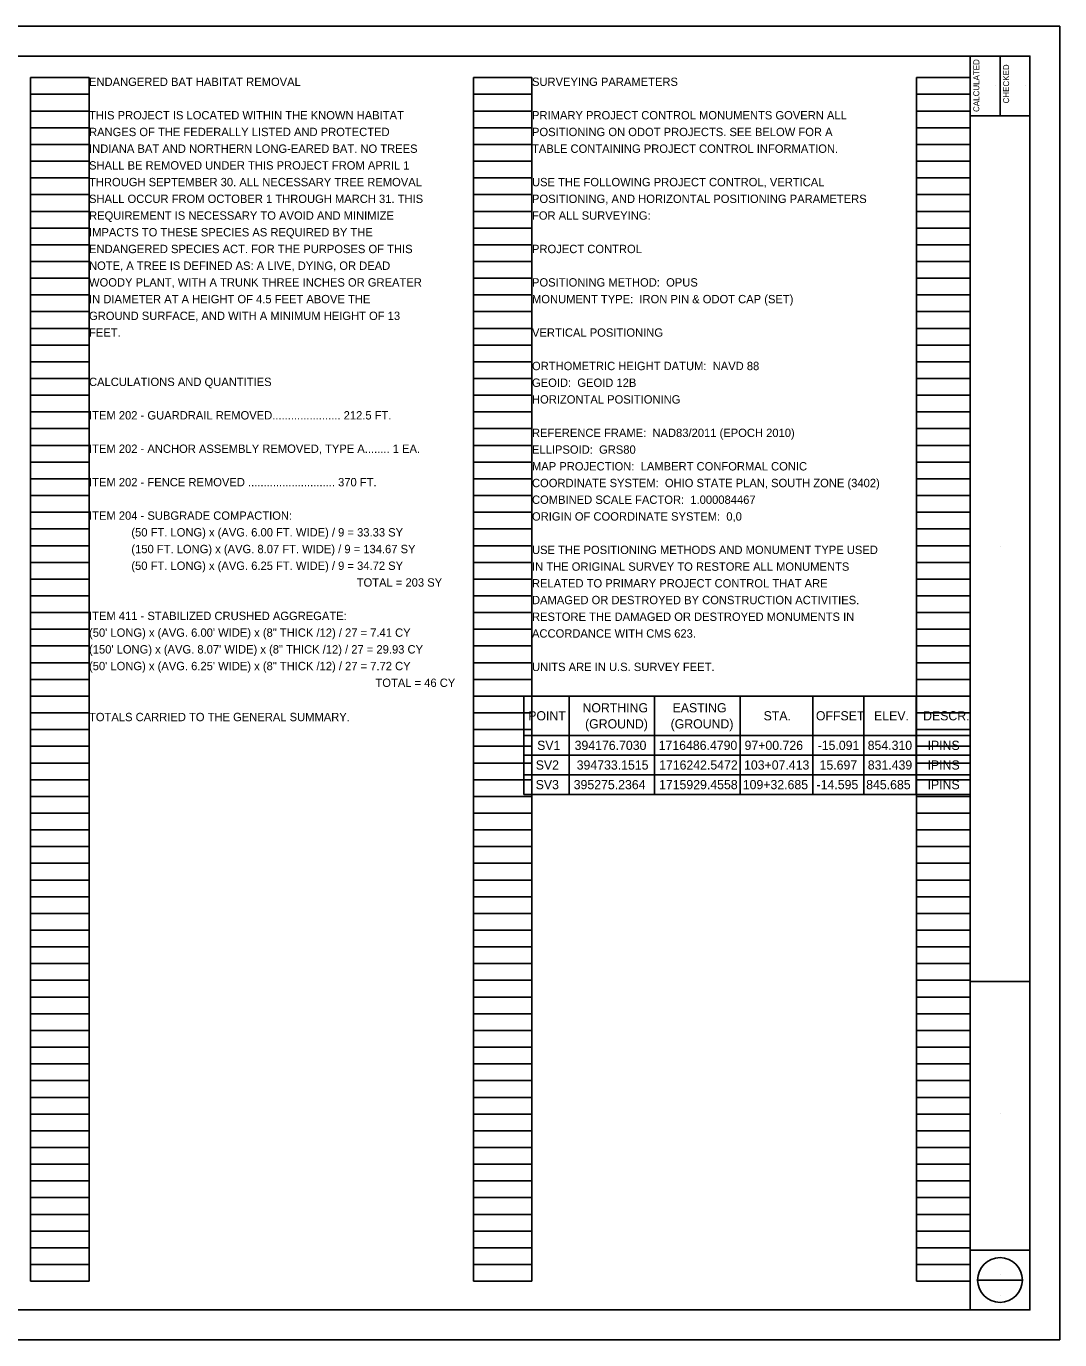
# Model space of a CAD drawing. Extents: x 0 to 34, y 0 to 22.
# Drawn here: x 16.69 to 34, y 0 to 22 of the extents above; entities that cross this region are included whole.
import ezdxf

# ---------------------------------------------------------------- set-up
doc = ezdxf.new("R2010")
doc.units = 0
for name, color, linetype in [('SH_Border', 7, 'Continuous'), ('SH_Cut_Line', 7, 'Continuous'), ('SH_Data', 7, 'Continuous'), ('SH_Text', 7, 'Continuous')]:
    doc.layers.add(name, color=color, linetype=linetype)

msp = doc.modelspace()

# ---------------------------------------------------------------- linework, layer by layer
at = {"layer": 'SH_Border'}
for p, q in [((32.5, 0.5), (32.5, 21.5)), ((33, 21.5), (33, 20.5)), ((32.5, 20.5), (33.5, 20.5)), ((32.5, 6), (33.5, 6)), ((32.5, 1.5), (33.5, 1.5))]:
    msp.add_line(p, q, dxfattribs=at)
msp.add_lwpolyline([(2, 21.5), (33.5, 21.5), (33.5, 0.5), (2, 0.5)], close=True, dxfattribs=at)
at = {"layer": 'SH_Cut_Line'}
msp.add_lwpolyline([(0, 0), (34, 0), (34, 22), (0, 22)], close=True, dxfattribs=at)
at = {"layer": 'SH_Data'}
for p, q in [((16.76, 0.98), (16.76, 21.14)), ((16.76, 21.14), (17.74, 21.14)), ((17.74, 0.98), (17.74, 21.14)), ((24.18, 0.98), (24.18, 21.14)), ((24.18, 21.14), (25.16, 21.14)), ((25.16, 0.98), (25.16, 21.14)), ((31.6, 0.98), (31.6, 21.14)), ((31.6, 21.14), (32.5, 21.14)), ((32.5, 0.98), (32.5, 21.14)), ((32.92, 21.004), (32.92, 21.004)), ((33.42, 21.004), (33.42, 21.004)), ((16.76, 20.86), (17.74, 20.86)), ((24.18, 20.86), (25.16, 20.86)), ((31.6, 20.86), (32.5, 20.86)), ((16.76, 20.58), (17.74, 20.58)), ((24.18, 20.58), (25.16, 20.58)), ((31.6, 20.58), (32.5, 20.58)), ((16.76, 20.3), (17.74, 20.3)), ((24.18, 20.3), (25.16, 20.3)), ((31.6, 20.3), (32.5, 20.3)), ((16.76, 20.02), (17.74, 20.02)), ((24.18, 20.02), (25.16, 20.02)), ((31.6, 20.02), (32.5, 20.02)), ((16.76, 19.74), (17.74, 19.74)), ((24.18, 19.74), (25.16, 19.74)), ((31.6, 19.74), (32.5, 19.74)), ((16.76, 19.46), (17.74, 19.46)), ((24.18, 19.46), (25.16, 19.46)), ((31.6, 19.46), (32.5, 19.46)), ((16.76, 19.18), (17.74, 19.18)), ((24.18, 19.18), (25.16, 19.18)), ((31.6, 19.18), (32.5, 19.18)), ((16.76, 18.9), (17.74, 18.9)), ((24.18, 18.9), (25.16, 18.9)), ((31.6, 18.9), (32.5, 18.9)), ((16.76, 18.62), (17.74, 18.62)), ((24.18, 18.62), (25.16, 18.62)), ((31.6, 18.62), (32.5, 18.62)), ((16.76, 18.34), (17.74, 18.34)), ((24.18, 18.34), (25.16, 18.34)), ((31.6, 18.34), (32.5, 18.34)), ((16.76, 18.06), (17.74, 18.06)), ((24.18, 18.06), (25.16, 18.06)), ((31.6, 18.06), (32.5, 18.06)), ((16.76, 17.78), (17.74, 17.78)), ((24.18, 17.78), (25.16, 17.78)), ((31.6, 17.78), (32.5, 17.78)), ((16.76, 17.5), (17.74, 17.5)), ((24.18, 17.5), (25.16, 17.5)), ((31.6, 17.5), (32.5, 17.5)), ((16.76, 17.22), (17.74, 17.22)), ((24.18, 17.22), (25.16, 17.22)), ((31.6, 17.22), (32.5, 17.22)), ((16.76, 16.94), (17.74, 16.94)), ((24.18, 16.94), (25.16, 16.94)), ((31.6, 16.94), (32.5, 16.94)), ((16.76, 16.66), (17.74, 16.66)), ((24.18, 16.66), (25.16, 16.66)), ((31.6, 16.66), (32.5, 16.66)), ((16.76, 16.38), (17.74, 16.38)), ((24.18, 16.38), (25.16, 16.38)), ((31.6, 16.38), (32.5, 16.38)), ((16.76, 16.1), (17.74, 16.1)), ((24.18, 16.1), (25.16, 16.1)), ((31.6, 16.1), (32.5, 16.1)), ((16.76, 15.82), (17.74, 15.82)), ((24.18, 15.82), (25.16, 15.82)), ((31.6, 15.82), (32.5, 15.82)), ((16.76, 15.54), (17.74, 15.54)), ((24.18, 15.54), (25.16, 15.54)), ((31.6, 15.54), (32.5, 15.54)), ((16.76, 15.26), (17.74, 15.26)), ((24.18, 15.26), (25.16, 15.26)), ((31.6, 15.26), (32.5, 15.26)), ((16.76, 14.98), (17.74, 14.98)), ((24.18, 14.98), (25.16, 14.98)), ((31.6, 14.98), (32.5, 14.98)), ((16.76, 14.7), (17.74, 14.7)), ((24.18, 14.7), (25.16, 14.7)), ((31.6, 14.7), (32.5, 14.7)), ((16.76, 14.42), (17.74, 14.42)), ((24.18, 14.42), (25.16, 14.42)), ((31.6, 14.42), (32.5, 14.42)), ((16.76, 14.14), (17.74, 14.14)), ((24.18, 14.14), (25.16, 14.14)), ((31.6, 14.14), (32.5, 14.14)), ((16.76, 13.86), (17.74, 13.86)), ((24.18, 13.86), (25.16, 13.86)), ((31.6, 13.86), (32.5, 13.86)), ((16.76, 13.58), (17.74, 13.58)), ((24.18, 13.58), (25.16, 13.58)), ((31.6, 13.58), (32.5, 13.58)), ((16.76, 13.3), (17.74, 13.3)), ((24.18, 13.3), (25.16, 13.3)), ((31.6, 13.3), (32.5, 13.3)), ((33, 13.292), (33, 13.292)), ((16.76, 13.02), (17.74, 13.02)), ((24.18, 13.02), (25.16, 13.02)), ((31.6, 13.02), (32.5, 13.02)), ((16.76, 12.74), (17.74, 12.74)), ((24.18, 12.74), (25.16, 12.74)), ((31.6, 12.74), (32.5, 12.74)), ((16.76, 12.46), (17.74, 12.46)), ((24.18, 12.46), (25.16, 12.46)), ((31.6, 12.46), (32.5, 12.46)), ((16.76, 12.18), (17.74, 12.18)), ((24.18, 12.18), (25.16, 12.18)), ((31.6, 12.18), (32.5, 12.18)), ((16.76, 11.9), (17.74, 11.9)), ((24.18, 11.9), (25.16, 11.9)), ((31.6, 11.9), (32.5, 11.9)), ((16.76, 11.62), (17.74, 11.62)), ((24.18, 11.62), (25.16, 11.62)), ((31.6, 11.62), (32.5, 11.62)), ((16.76, 11.34), (17.74, 11.34)), ((24.18, 11.34), (25.16, 11.34)), ((31.6, 11.34), (32.5, 11.34)), ((16.76, 11.06), (17.74, 11.06)), ((24.18, 11.06), (25.16, 11.06)), ((31.6, 11.06), (32.5, 11.06)), ((16.76, 10.78), (17.74, 10.78)), ((24.18, 10.78), (25.16, 10.78)), ((25.022, 10.78), (32.5, 10.78)), ((25.022, 10.78), (25.022, 9.133)), ((25.78, 10.78), (25.78, 9.133)), ((27.213, 10.78), (27.213, 9.133)), ((28.646, 10.78), (28.646, 9.133)), ((29.865, 10.78), (29.865, 9.133)), ((30.721, 10.78), (30.721, 9.133)), ((31.594, 10.78), (31.594, 9.133)), ((31.6, 10.78), (32.5, 10.78)), ((32.5, 10.78), (32.5, 9.133)), ((16.76, 10.5), (17.74, 10.5)), ((24.18, 10.5), (25.16, 10.5)), ((31.6, 10.5), (32.5, 10.5)), ((16.76, 10.22), (17.74, 10.22)), ((24.18, 10.22), (25.16, 10.22)), ((25.022, 10.121), (32.5, 10.121)), ((31.6, 10.22), (32.5, 10.22)), ((16.76, 9.94), (17.74, 9.94)), ((24.18, 9.94), (25.16, 9.94)), ((31.6, 9.94), (32.5, 9.94)), ((25.022, 9.792), (32.5, 9.792)), ((16.76, 9.66), (17.74, 9.66)), ((24.18, 9.66), (25.16, 9.66)), ((25.022, 9.462), (32.5, 9.462)), ((31.6, 9.66), (32.5, 9.66)), ((16.76, 9.38), (17.74, 9.38)), ((24.18, 9.38), (25.16, 9.38)), ((31.6, 9.38), (32.5, 9.38)), ((16.76, 9.1), (17.74, 9.1)), ((24.18, 9.1), (25.16, 9.1)), ((25.022, 9.133), (32.5, 9.133)), ((31.6, 9.1), (32.5, 9.1)), ((16.76, 8.82), (17.74, 8.82)), ((24.18, 8.82), (25.16, 8.82)), ((31.6, 8.82), (32.5, 8.82)), ((16.76, 8.54), (17.74, 8.54)), ((24.18, 8.54), (25.16, 8.54)), ((31.6, 8.54), (32.5, 8.54)), ((16.76, 8.26), (17.74, 8.26)), ((24.18, 8.26), (25.16, 8.26)), ((31.6, 8.26), (32.5, 8.26)), ((16.76, 7.98), (17.74, 7.98)), ((24.18, 7.98), (25.16, 7.98)), ((31.6, 7.98), (32.5, 7.98)), ((16.76, 7.7), (17.74, 7.7)), ((24.18, 7.7), (25.16, 7.7)), ((31.6, 7.7), (32.5, 7.7)), ((16.76, 7.42), (17.74, 7.42)), ((24.18, 7.42), (25.16, 7.42)), ((31.6, 7.42), (32.5, 7.42)), ((16.76, 7.14), (17.74, 7.14)), ((24.18, 7.14), (25.16, 7.14)), ((31.6, 7.14), (32.5, 7.14)), ((16.76, 6.86), (17.74, 6.86)), ((24.18, 6.86), (25.16, 6.86)), ((31.6, 6.86), (32.5, 6.86)), ((16.76, 6.58), (17.74, 6.58)), ((24.18, 6.58), (25.16, 6.58)), ((31.6, 6.58), (32.5, 6.58)), ((16.76, 6.3), (17.74, 6.3)), ((24.18, 6.3), (25.16, 6.3)), ((31.6, 6.3), (32.5, 6.3)), ((16.76, 6.02), (17.74, 6.02)), ((24.18, 6.02), (25.16, 6.02)), ((31.6, 6.02), (32.5, 6.02)), ((16.76, 5.74), (17.74, 5.74)), ((24.18, 5.74), (25.16, 5.74)), ((31.6, 5.74), (32.5, 5.74)), ((16.76, 5.46), (17.74, 5.46)), ((24.18, 5.46), (25.16, 5.46)), ((31.6, 5.46), (32.5, 5.46)), ((16.76, 5.18), (17.74, 5.18)), ((24.18, 5.18), (25.16, 5.18)), ((31.6, 5.18), (32.5, 5.18)), ((16.76, 4.9), (17.74, 4.9)), ((24.18, 4.9), (25.16, 4.9)), ((31.6, 4.9), (32.5, 4.9)), ((16.76, 4.62), (17.74, 4.62)), ((24.18, 4.62), (25.16, 4.62)), ((31.6, 4.62), (32.5, 4.62)), ((16.76, 4.34), (17.74, 4.34)), ((24.18, 4.34), (25.16, 4.34)), ((31.6, 4.34), (32.5, 4.34)), ((16.76, 4.06), (17.74, 4.06)), ((24.18, 4.06), (25.16, 4.06)), ((31.6, 4.06), (32.5, 4.06)), ((16.76, 3.78), (17.74, 3.78)), ((24.18, 3.78), (25.16, 3.78)), ((31.6, 3.78), (32.5, 3.78)), ((33, 3.792), (33, 3.792)), ((16.76, 3.5), (17.74, 3.5)), ((24.18, 3.5), (25.16, 3.5)), ((31.6, 3.5), (32.5, 3.5)), ((16.76, 3.22), (17.74, 3.22)), ((24.18, 3.22), (25.16, 3.22)), ((31.6, 3.22), (32.5, 3.22)), ((16.76, 2.94), (17.74, 2.94)), ((24.18, 2.94), (25.16, 2.94)), ((31.6, 2.94), (32.5, 2.94)), ((16.76, 2.66), (17.74, 2.66)), ((24.18, 2.66), (25.16, 2.66)), ((31.6, 2.66), (32.5, 2.66)), ((16.76, 2.38), (17.74, 2.38)), ((24.18, 2.38), (25.16, 2.38)), ((31.6, 2.38), (32.5, 2.38)), ((16.76, 2.1), (17.74, 2.1)), ((24.18, 2.1), (25.16, 2.1)), ((31.6, 2.1), (32.5, 2.1)), ((16.76, 1.82), (17.74, 1.82)), ((24.18, 1.82), (25.16, 1.82)), ((31.6, 1.82), (32.5, 1.82)), ((16.76, 1.54), (17.74, 1.54)), ((24.18, 1.54), (25.16, 1.54)), ((31.6, 1.54), (32.5, 1.54)), ((16.76, 1.26), (17.74, 1.26)), ((24.18, 1.26), (25.16, 1.26)), ((31.6, 1.26), (32.5, 1.26)), ((16.76, 0.98), (17.74, 0.98)), ((24.18, 0.98), (25.16, 0.98)), ((31.6, 0.98), (32.5, 0.98)), ((32.625, 1), (33.375, 1)), ((33, 1.085), (33, 1.085)), ((33, 0.745), (33, 0.745))]:
    msp.add_line(p, q, dxfattribs=at)
msp.add_circle((33, 1), 0.375, dxfattribs=at)

# ---------------------------------------------------------------- texts
for s, p in [('CALCULATED', (32.652, 20.565)), ('CHECKED', (33.152, 20.708))]:
    msp.add_text(s, height=0.1, rotation=90, dxfattribs=at).set_placement(p)
at = {"layer": 'SH_Text'}
for s, height, p in [('ENDANGERED BAT HABITAT REMOVAL', 0.14, (17.74, 21)), ('SURVEYING PARAMETERS', 0.14, (25.16, 21)), ('THIS PROJECT IS LOCATED WITHIN THE KNOWN HABITAT', 0.14, (17.74, 20.44)), ('PRIMARY PROJECT CONTROL MONUMENTS GOVERN ALL', 0.14, (25.16, 20.44)), ('RANGES OF THE FEDERALLY LISTED AND PROTECTED', 0.14, (17.74, 20.16)), ('POSITIONING ON ODOT PROJECTS. SEE BELOW FOR A', 0.14, (25.16, 20.16)), ('INDIANA BAT AND NORTHERN LONG-EARED BAT. NO TREES', 0.14, (17.74, 19.88)), ('TABLE CONTAINING PROJECT CONTROL INFORMATION.', 0.14, (25.16, 19.88)), ('SHALL BE REMOVED UNDER THIS PROJECT FROM APRIL 1', 0.14, (17.74, 19.6)), ('THROUGH SEPTEMBER 30. ALL NECESSARY TREE REMOVAL', 0.14, (17.74, 19.32)), ('USE THE FOLLOWING PROJECT CONTROL, VERTICAL', 0.14, (25.16, 19.32)), ('SHALL OCCUR FROM OCTOBER 1 THROUGH MARCH 31. THIS', 0.14, (17.74, 19.04)), ('POSITIONING, AND HORIZONTAL POSITIONING PARAMETERS', 0.14, (25.16, 19.04)), ('REQUIREMENT IS NECESSARY TO AVOID AND MINIMIZE', 0.14, (17.74, 18.76)), ('FOR ALL SURVEYING:', 0.14, (25.16, 18.76)), ('IMPACTS TO THESE SPECIES AS REQUIRED BY THE', 0.14, (17.74, 18.48)), ('ENDANGERED SPECIES ACT. FOR THE PURPOSES OF THIS', 0.14, (17.74, 18.2)), ('PROJECT CONTROL', 0.14, (25.16, 18.2)), ('NOTE, A TREE IS DEFINED AS: A LIVE, DYING, OR DEAD', 0.14, (17.74, 17.92)), ('WOODY PLANT, WITH A TRUNK THREE INCHES OR GREATER', 0.14, (17.74, 17.64)), ('POSITIONING METHOD:  OPUS', 0.14, (25.16, 17.64)), ('IN DIAMETER AT A HEIGHT OF 4.5 FEET ABOVE THE', 0.14, (17.74, 17.36)), ('MONUMENT TYPE:  IRON PIN & ODOT CAP (SET)', 0.14, (25.16, 17.36)), ('GROUND SURFACE, AND WITH A MINIMUM HEIGHT OF 13', 0.14, (17.74, 17.08)), ('FEET.', 0.14, (17.74, 16.8)), ('VERTICAL POSITIONING', 0.14, (25.16, 16.8)), ('ORTHOMETRIC HEIGHT DATUM:  NAVD 88', 0.14, (25.16, 16.24)), ('CALCULATIONS AND QUANTITIES', 0.14, (17.74, 15.974)), ('GEOID:  GEOID 12B', 0.14, (25.16, 15.96)), ('HORIZONTAL POSITIONING', 0.14, (25.16, 15.68)), ('ITEM 202 - GUARDRAIL REMOVED...................... 212.5 FT.', 0.14, (17.74, 15.414)), ('REFERENCE FRAME:  NAD83/2011 (EPOCH 2010)', 0.14, (25.16, 15.12)), ('ITEM 202 - ANCHOR ASSEMBLY REMOVED, TYPE A........ 1 EA.', 0.14, (17.74, 14.854)), ('ELLIPSOID:  GRS80', 0.14, (25.16, 14.84)), ('MAP PROJECTION:  LAMBERT CONFORMAL CONIC', 0.14, (25.16, 14.56)), ('ITEM 202 - FENCE REMOVED ............................ 370 FT.', 0.14, (17.74, 14.294)), ('COORDINATE SYSTEM:  OHIO STATE PLAN, SOUTH ZONE (3402)', 0.14, (25.16, 14.28)), ('COMBINED SCALE FACTOR:  1.000084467', 0.14, (25.16, 14)), ('ITEM 204 - SUBGRADE COMPACTION:', 0.14, (17.74, 13.734)), ('ORIGIN OF COORDINATE SYSTEM:  0,0', 0.14, (25.16, 13.72)), ('(50 FT. LONG) x (AVG. 6.00 FT. WIDE) / 9 = 33.33 SY', 0.14, (18.449, 13.454)), ('(150 FT. LONG) x (AVG. 8.07 FT. WIDE) / 9 = 134.67 SY', 0.14, (18.449, 13.174)), ('USE THE POSITIONING METHODS AND MONUMENT TYPE USED', 0.14, (25.16, 13.16)), ('(50 FT. LONG) x (AVG. 6.25 FT. WIDE) / 9 = 34.72 SY', 0.14, (18.449, 12.894)), ('IN THE ORIGINAL SURVEY TO RESTORE ALL MONUMENTS', 0.14, (25.16, 12.88)), ('TOTAL = 203 SY', 0.14, (22.224, 12.614)), ('RELATED TO PRIMARY PROJECT CONTROL THAT ARE', 0.14, (25.16, 12.6)), ('DAMAGED OR DESTROYED BY CONSTRUCTION ACTIVITIES.', 0.14, (25.16, 12.32)), ('ITEM 411 - STABILIZED CRUSHED AGGREGATE:', 0.14, (17.74, 12.054)), ('RESTORE THE DAMAGED OR DESTROYED MONUMENTS IN', 0.14, (25.16, 12.04)), ('(50\' LONG) x (AVG. 6.00\' WIDE) x (8" THICK /12) / 27 = 7.41 CY', 0.14, (17.74, 11.774)), ('ACCORDANCE WITH CMS 623.', 0.14, (25.16, 11.76)), ('(150\' LONG) x (AVG. 8.07\' WIDE) x (8" THICK /12) / 27 = 29.93 CY', 0.14, (17.74, 11.494)), ('(50\' LONG) x (AVG. 6.25\' WIDE) x (8" THICK /12) / 27 = 7.72 CY', 0.14, (17.74, 11.214)), ('UNITS ARE IN U.S. SURVEY FEET.', 0.14, (25.16, 11.2)), ('TOTAL = 46 CY', 0.14, (22.538, 10.934)), ('NORTHING', 0.154, (26.006, 10.508)), ('EASTING', 0.154, (27.515, 10.508)), ('TOTALS CARRIED TO THE GENERAL SUMMARY.', 0.14, (17.74, 10.36)), ('POINT', 0.154, (25.097, 10.374)), ('(GROUND)', 0.154, (26.049, 10.239)), ('(GROUND)', 0.154, (27.482, 10.239)), ('STA.', 0.154, (29.04, 10.374)), ('OFFSET', 0.154, (29.916, 10.374)), ('ELEV.', 0.154, (30.89, 10.374)), ('DESCR.', 0.154, (31.712, 10.374)), ('SV1', 0.154, (25.246, 9.879)), ('394176.7030', 0.154, (25.874, 9.879)), ('1716486.4790', 0.154, (27.282, 9.879)), ('97+00.726', 0.154, (28.721, 9.879)), ('-15.091', 0.154, (29.945, 9.879)), ('854.310', 0.154, (30.783, 9.879)), ('IPINS', 0.154, (31.786, 9.879)), ('SV2', 0.154, (25.223, 9.55)), ('394733.1515', 0.154, (25.909, 9.55)), ('1716242.5472', 0.154, (27.289, 9.55)), ('103+07.413', 0.154, (28.712, 9.55)), ('15.697', 0.154, (29.977, 9.55)), ('831.439', 0.154, (30.785, 9.55)), ('IPINS', 0.154, (31.786, 9.55)), ('SV3', 0.154, (25.222, 9.221)), ('395275.2364', 0.154, (25.859, 9.221)), ('1715929.4558', 0.154, (27.288, 9.221)), ('109+32.685', 0.154, (28.691, 9.221)), ('-14.595', 0.154, (29.927, 9.221)), ('845.685', 0.154, (30.758, 9.221)), ('IPINS', 0.154, (31.786, 9.221))]:
    msp.add_text(s, height=height, dxfattribs=at).set_placement(p)

doc.saveas('drawing.dxf')
